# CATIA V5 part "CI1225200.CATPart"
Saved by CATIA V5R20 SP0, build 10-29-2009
Part number: CI1225200
Bounding box of the stored display mesh (mm): x -24 to 24, y -20.022 to 234.5, z -27.733 to 28.158
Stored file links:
  C:\Users\Raffaele\Desktop\3D X SITO CF\BOLEX\19-INCLINED ASSEMBLY REF_CI\CI1225200.CATPart
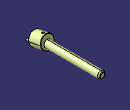
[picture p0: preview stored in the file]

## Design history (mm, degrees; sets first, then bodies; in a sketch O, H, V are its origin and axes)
Set1
  DatumSurface1 to DatumSurface16 "MANIFOLD_SOLID_BREP #393"
  DatumSurface17 to DatumSurface39 "MANIFOLD_SOLID_BREP #1138"
Body1 (main body)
